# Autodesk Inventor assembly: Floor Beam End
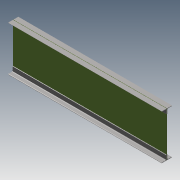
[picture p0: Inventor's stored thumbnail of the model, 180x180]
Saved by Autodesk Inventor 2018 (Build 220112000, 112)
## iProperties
Created: 2018-02
Part Number: Floor Beam End
Document SubType Name: Assembly
Designer: STK
Mass: 1.14131e+06 g
Surface Area: 239531 cm^2
Volume: 145390 cm^3
Density: 7.85 g/cm^3
Author: STK
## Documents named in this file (4)
- D:\SolidWorks\Through Truss\Floor Beam_End\Floor Beam End.iam
- D:\SolidWorks\Through Truss\Floor Beam_End\Web_FB_end.ipt
- D:\SolidWorks\Through Truss\Floor Beam_End\Top Flange Angle_FB_End.ipt
- D:\SolidWorks\Through Truss\Floor Beam_End\Top Flange Angle_FB_End\Top Flange Angle_FB_End-01.ipt
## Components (5 placed, 2 different names)
1. Web_FB_end:1 — Mate:1, Flush:1, Mate:2, Mate:3, Flush:2, Flush:3, Mate:4, Mate:5, Flush:7, Mate:6
2. Top Flange Angle_FB_End-01:1 — Mate:3, Flush:2, Flush:3, Flush:4, Flush:5, Flush:6
3. Top Flange Angle_FB_End-01:2 — Mate:4, Flush:4, Flush:5
4. Top Flange Angle_FB_End-01:3 — Mate:5, Flush:6, Flush:7, Flush:8, Flush:9
5. Top Flange Angle_FB_End-01:4 — Mate:6, Flush:8, Flush:9
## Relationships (15: Flush 9, Mate 6)
- Mate:1: Web_FB_end:1
- Flush:1: Web_FB_end:1
- Mate:2: Web_FB_end:1
- Mate:3: Web_FB_end:1 ↔ Top Flange Angle_FB_End-01:1
- Flush:2: Web_FB_end:1 ↔ Top Flange Angle_FB_End-01:1
- Flush:3: Web_FB_end:1 ↔ Top Flange Angle_FB_End-01:1
- Mate:4: Web_FB_end:1 ↔ Top Flange Angle_FB_End-01:2
- Flush:4: Top Flange Angle_FB_End-01:1 ↔ Top Flange Angle_FB_End-01:2
- Flush:5: Top Flange Angle_FB_End-01:1 ↔ Top Flange Angle_FB_End-01:2
- Mate:5: Web_FB_end:1 ↔ Top Flange Angle_FB_End-01:3
- Flush:6: Top Flange Angle_FB_End-01:1 ↔ Top Flange Angle_FB_End-01:3
- Flush:7: Web_FB_end:1 ↔ Top Flange Angle_FB_End-01:3
- Mate:6: Web_FB_end:1 ↔ Top Flange Angle_FB_End-01:4
- Flush:8: Top Flange Angle_FB_End-01:3 ↔ Top Flange Angle_FB_End-01:4
- Flush:9: Top Flange Angle_FB_End-01:3 ↔ Top Flange Angle_FB_End-01:4
## Named parameters: sa_0 = 1.11796e+08 mm, sa_1 = 1066.8 mm, sa_2 = 1371.6 mm, sa_3 = 0, sa_4 = 1.11796e+08 mm, sa_5 = -1066.8 mm, sa_6 = 1371.6 mm, sa_7 = 0
